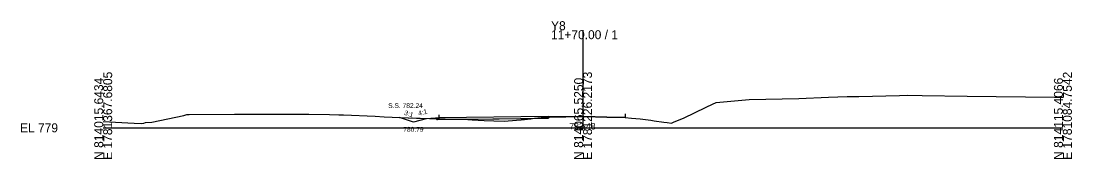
# Model space of a CAD drawing. Extents: x -26 to 303, y -10 to 5036.
# Drawn here: x -25.7 to 302.8, y 2490.3 to 2533.3 of the extents above; entities that cross this region are included whole.
import ezdxf

# ---------------------------------------------------------------- set-up
doc = ezdxf.new("R2010")
doc.units = 0
for name, color, linetype in [('Exist Cross Section Cell', 7, 'Continuous'), ('Exist XS Center Line Elevation Label', 7, 'Continuous'), ('Exist XS Ground Line', 7, 'Continuous'), ('Prop XS Ditch Slope Text', 7, 'Continuous'), ('Prop XS Ditch Standard Text', 7, 'Continuous'), ('Prop XS Dump Level', 7, 'Continuous'), ('Prop XS Earthwork Shape', 7, 'Continuous'), ('Prop XS EOT Tick Mark', 7, 'Continuous'), ('Prop XS Finish Grade', 7, 'Continuous'), ('Prop XS Finish Grade Earthwork', 7, 'Continuous'), ('Prop XS Finish Grade Pavement', 7, 'Continuous'), ('Prop XS Pvmt Edge Slope', 7, 'Continuous'), ('Prop XS Side Slope Text', 7, 'Continuous'), ('Prop XS SS Elevation Text', 7, 'Continuous'), ('Prop XS Subgrade Earthwork', 7, 'Continuous')]:
    doc.layers.add(name, color=color, linetype=linetype)

msp = doc.modelspace()

# ---------------------------------------------------------------- linework, layer by layer
at = {"layer": 'Exist Cross Section Cell'}
for p, q in [((150, 2500), (150, 2530.42)), ((0, 2500), (150, 2500)), ((150, 2500), (300, 2500))]:
    msp.add_line(p, q, dxfattribs=at)
at = {"layer": 'Exist XS Ground Line'}
for p, q in [((236.26, 2509.81), (248.96, 2510.04)), ((248.96, 2510.04), (251.27, 2510.14)), ((251.27, 2510.14), (255.98, 2510.08)), ((255.98, 2510.08), (270.05, 2509.84)), ((188.47, 2506.47), (190.48, 2507.42)), ((190.48, 2507.42), (191.62, 2507.91)), ((191.62, 2507.91), (201.92, 2508.83)), ((201.92, 2508.83), (217.43, 2509.14)), ((217.43, 2509.14), (226.73, 2509.54)), ((226.73, 2509.54), (232.52, 2509.75)), ((232.52, 2509.75), (236.26, 2509.81)), ((270.05, 2509.84), (297.38, 2509.58)), ((297.38, 2509.58), (300, 2509.52)), ((15.24, 2501.81), (25.19, 2503.86)), ((25.19, 2503.86), (26.15, 2504.12)), ((26.15, 2504.12), (26.46, 2504.13)), ((26.46, 2504.13), (26.82, 2504.14)), ((26.82, 2504.14), (41.07, 2504.29)), ((41.07, 2504.29), (43.88, 2504.21)), ((43.88, 2504.21), (52.79, 2504.26)), ((52.79, 2504.26), (54.69, 2504.25)), ((54.69, 2504.25), (57.9, 2504.23)), ((57.9, 2504.23), (64.29, 2504.22)), ((64.29, 2504.22), (70.77, 2504.11)), ((70.77, 2504.11), (73.69, 2504.04)), ((73.69, 2504.04), (75.12, 2504.06)), ((75.12, 2504.06), (85, 2503.63)), ((85, 2503.63), (87.87, 2503.42)), ((87.87, 2503.42), (97.93, 2503.04)), ((139.08, 2503.35), (150.27, 2503.49)), ((150.27, 2503.49), (157.45, 2503.32)), ((181.37, 2503.05), (188.47, 2506.47)), ((0, 2501.97), (9.72, 2501.46)), ((9.72, 2501.46), (11.83, 2501.35)), ((11.83, 2501.35), (12.68, 2501.46)), ((12.68, 2501.46), (13.2, 2501.61)), ((13.2, 2501.61), (15.24, 2501.81)), ((97.93, 2503.04), (98.53, 2503.02)), ((98.53, 2503.02), (99.09, 2503.01)), ((99.09, 2503.01), (101.99, 2502.94)), ((101.99, 2502.94), (105.13, 2502.85)), ((105.13, 2502.85), (105.9, 2502.85)), ((105.9, 2502.85), (106.92, 2502.81)), ((106.92, 2502.81), (113, 2502.66)), ((113, 2502.66), (115.31, 2502.52)), ((115.31, 2502.52), (119.04, 2502.28)), ((119.04, 2502.28), (122.11, 2502.2)), ((122.11, 2502.2), (125.37, 2502.12)), ((125.37, 2502.12), (129.24, 2502.37)), ((129.24, 2502.37), (130.68, 2502.49)), ((130.68, 2502.49), (134.86, 2502.97)), ((134.86, 2502.97), (136.93, 2503.18)), ((136.93, 2503.18), (139.08, 2503.35)), ((157.45, 2503.32), (163.21, 2503.19)), ((163.21, 2503.19), (165.13, 2503.04)), ((165.13, 2503.04), (167.9, 2502.85)), ((167.9, 2502.85), (171.19, 2502.36)), ((171.19, 2502.36), (172.19, 2502.21)), ((172.19, 2502.21), (175.28, 2501.73)), ((175.28, 2501.73), (176.27, 2501.62)), ((176.27, 2501.62), (177.63, 2501.5)), ((177.63, 2501.5), (178.53, 2501.91)), ((178.53, 2501.91), (181.37, 2503.05))]:
    msp.add_line(p, q, dxfattribs=at)
at = {"layer": 'Prop XS Earthwork Shape'}
for points in [[(92.66, 2503.24), (97.93, 2503.04), (98.53, 2503.02), (99.09, 2503.01), (101.99, 2502.94), (102.8, 2502.92), (101, 2502.79), (97, 2501.79)], [(104.01, 2502.89), (103.9, 2503), (102.8, 2502.92)], [(113.93, 2502.6), (104.41, 2502.49), (104.01, 2502.89), (105.13, 2502.85), (105.9, 2502.85), (106.92, 2502.81), (113, 2502.66)], [(133.66, 2502.83), (113.93, 2502.6), (115.31, 2502.52), (119.04, 2502.28), (122.11, 2502.2), (125.37, 2502.12), (129.24, 2502.37), (130.68, 2502.49)], [(133.66, 2502.83), (134.86, 2502.97), (136.93, 2503.18), (139.08, 2503.35), (139.08, 2502.9)]]:
    msp.add_lwpolyline(points, close=True, dxfattribs=at)
at = {"layer": 'Prop XS EOT Tick Mark'}
for p, q in [((105, 2503.08), (105, 2504.08)), ((163.22, 2503.32), (163.22, 2504.32))]:
    msp.add_line(p, q, dxfattribs=at)
at = {"layer": 'Prop XS Finish Grade'}
msp.add_line((105, 2503.08), (103.9, 2503), dxfattribs=at)
at = {"layer": 'Prop XS Finish Grade Earthwork'}
for p, q in [((97, 2501.79), (92.66, 2503.24)), ((101, 2502.79), (97, 2501.79)), ((103.9, 2503), (101, 2502.79))]:
    msp.add_line(p, q, dxfattribs=at)
at = {"layer": 'Prop XS Finish Grade Pavement'}
for p, q in [((139.08, 2503.48), (105, 2503.08)), ((139.08, 2503.48), (150.27, 2503.61)), ((139.08, 2503.48), (139.09, 2503.35)), ((150.27, 2503.61), (157.45, 2503.45)), ((157.45, 2503.45), (163.22, 2503.32))]:
    msp.add_line(p, q, dxfattribs=at)
at = {"layer": 'Prop XS Pvmt Edge Slope'}
msp.add_line((105, 2503.08), (104.41, 2502.49), dxfattribs=at)
at = {"layer": 'Prop XS Subgrade Earthwork'}
for p, q in [((104.41, 2502.49), (103.9, 2503)), ((139.08, 2502.9), (104.41, 2502.49)), ((139.08, 2502.9), (139.08, 2503.35))]:
    msp.add_line(p, q, dxfattribs=at)

# ---------------------------------------------------------------- texts
at = {"layer": 'Exist Cross Section Cell'}
for s, p in [('Y8', (140, 2530.42)), ('11+70.00 / 1', (140, 2527.62)), ('EL 779', (-26, 2498.6))]:
    msp.add_text(s, height=2.8, dxfattribs=at).set_placement(p)
for s, p in [('E 1781367.6805', (2.8, 2490)), ('E 1781226.2173', (152.8, 2490)), ('E 1781084.7542', (302.8, 2490)), ('N 814015.6434', (0, 2490)), ('N 814065.5250', (150, 2490)), ('N 814115.4066', (300, 2490))]:
    msp.add_text(s, height=2.8, rotation=90, dxfattribs=at).set_placement(p)
at = {"layer": 'Exist XS Center Line Elevation Label'}
msp.add_text('782.48', height=2, dxfattribs=at).set_placement((145.73, 2499.48))
at = {"layer": 'Prop XS Ditch Slope Text'}
msp.add_text('4:1', height=1.5, rotation=14.0362, dxfattribs=at).set_placement((98.64, 2503.75))
at = {"layer": 'Prop XS Ditch Standard Text'}
msp.add_text('780.79', height=1.5, dxfattribs=at).set_placement((93.8, 2498.79))
at = {"layer": 'Prop XS Dump Level'}
for s, height, p in [('Case1', 0.04, (101, 2502.75)), ('Eop', 0.3, (139.08, 2503.05))]:
    msp.add_text(s, height=height, dxfattribs=at).set_placement(p)
at = {"layer": 'Prop XS Side Slope Text'}
msp.add_text('3:1', height=1.5, rotation=341.5651, dxfattribs=at).set_placement((93.95, 2504.1))
at = {"layer": 'Prop XS SS Elevation Text'}
msp.add_text('S.S. 782.24', height=1.5, dxfattribs=at).set_placement((89.09, 2506.18))

doc.saveas('drawing.dxf')
